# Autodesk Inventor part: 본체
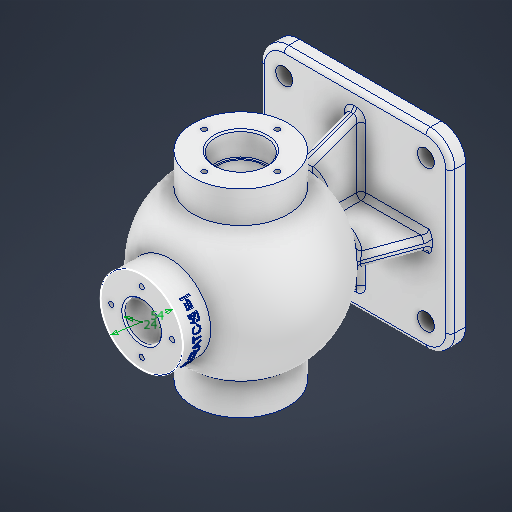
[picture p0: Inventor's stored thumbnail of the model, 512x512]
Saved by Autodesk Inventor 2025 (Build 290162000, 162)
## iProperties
Created: 2025-08
Part Number: 본체
Material: 알루미늄 6061
Document SubType Name: Modeling
Designer: infra012
Density: 2.7 g/cm^3
Appearance: 알루미늄 - 평지
Mass: 1540.2 g
Surface Area: 1173.87 cm^2
Volume: 570.444 cm^3
Author: infra012
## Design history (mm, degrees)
sketch "스케치2"
  geometry: L1 (-62.5, -62.5)-(62.5, -62.5); L2 (62.5, -62.5)-(62.5, 62.5); L3 (62.5, 62.5)-(-62.5, 62.5); L4 (-62.5, 62.5)-(-62.5, -62.5); L5 (-62.5, -62.5)-(62.5, 62.5); L6 (62.5, -62.5)-(-62.5, 62.5); 1 further point
  constraints: 12 end point, 2 midpoint, 2 parallel, 1 horizontal, 1 perpendicular
  dimensions: "d0" = 125 distance of L3.end L2.end; "d1" = 125 distance of L2.end L1.end
extrude "돌출1" new body sketch "스케치2" distance "d2" = 10; taper "d3" = 0 deg
sketch "스케치3"
  geometry: L1 (8.5, 85)-(116.5, 85); L2 (0, 0)-(125, 0) reference; A1 r 44 centre (62.5, 85) between (106.5, 85) and (18.5, 85); A2 r 54 centre (62.5, 85) between (116.5, 85) and (8.5, 85); 3 further points
  constraints: 4 point on circle, 2 centre point, 2 end point, 2 point on line, 1 coincident, 1 horizontal alignment, 1 midpoint
  dimensions: "d4" = 88 diameter of A1; "d5" = 108 diameter of A2; "d7" = 85 distance from line of L2 A1.centre
revolve "회전1" sketch "스케치3" stored, may be unused: angle "d8" = 90 deg
node "작업 평면1"
sketch "스케치4"
  geometry: C1 r 27 at (0, 0); C2 r 12 at (0, 0); 1 further point
  constraints: 2 centre point, 2 coincident
  dimensions: "d10" = 54 diameter of C1; "d11" = 24 diameter of C2
extrude "돌출2" join sketch "스케치4" stored distance "d12" = 10; taper "d13" = 0 deg
node "작업 평면3"
sketch "스케치5"
  geometry: L1 (-27, 131.765)-(27, 131.765) reference; C1 r 31 at (0, 85); A1 r 54 centre (0, 85) between (-27, 131.765) and (27, 131.765) reference; 1 further point
  constraints: 1 centre point, 1 coincident
  dimensions: "d16" = 62 diameter of C1
extrude "돌출3" join sketch "스케치5" stored distance "d18" = 10; taper "d19" = 0 deg
node "작업 평면4"
sketch "스케치6"
  geometry: C1 r 31 at (0, 85) reference; 1 further point
extrude "돌출4" join sketch "스케치6" stored distance "d21" = 10; taper "d22" = 0 deg
sketch "스케치7"
  geometry: C1 r 31 at (0, 0) reference; C2 r 15 at (0, 0); 1 further point
  constraints: 1 centre point, 1 coincident
  dimensions: "d23" = 30 diameter of C2
extrude "돌출5" cut sketch "스케치7" extent not by distance; stored distance "d24" = 0; taper "d25" = 0 deg
sketch "스케치8"
  geometry: C1 r 31 at (0, 0) reference; C2 r 16.5 at (0, 0); 1 further point
  constraints: 1 centre point, 1 coincident
  dimensions: "d26" = 33 diameter of C2
hole "구멍1" sketch "스케치8" at (0, 0) diameter "d27" = 33; stored, may be unused: countersink angle "d31" = 90 deg, drill point angle "d33" = 0 deg; dims "d28" = 12, "d29" = 33, "d30" = 1, "d32" = 16
sketch "스케치9"
  geometry: C1 r 16.5 at (0, 0) reference; 1 further point
hole "구멍2" sketch "스케치9" at (0, 0) diameter "d34" = 33; stored, may be unused: countersink angle "d38" = 90 deg, drill point angle "d40" = 0 deg; dims "d35" = 6, "d36" = 4, "d37" = 2, "d39" = 16
hole "구멍3" sketch "스케치4" diameter "d41" = 24; stored, may be unused: countersink angle "d45" = 90 deg, drill point angle "d47" = 0 deg; dims "d42" = 6, "d43" = 4, "d44" = 2, "d46" = 84.075
sketch "스케치11"
  geometry: L1 (-33.559, 56.544)-(-50.5, 10); L2 (33.559, 56.544)-(50.5, 10); L3 (-62.5, 0)-(-62.5, 10) reference; L4 (62.5, 0)-(62.5, 10) reference; L5 (62.5, 10)-(-62.5, 10) reference; A1 r 44 centre (0, 85) between (-41.364, 70) and (-41.364, 100) reference; 1 further point
  constraints: 4 end point, 2 point on circle, 2 point on line
  dimensions: "d48" = 20 deg angle of L3 L1; "d49" = 20 deg angle of L4 L2; "d50" = 12 distance from line of L1.end L3; "d51" = 12 distance from line of L4 L2.end
sketch "스케치12"
  geometry: L1 (-33.559, 56.544)-(-50.5, 10); L2 (33.559, 56.544)-(50.5, 10); L3 (-62.5, 0)-(-62.5, 10) reference; L4 (62.5, 0)-(62.5, 10) reference; L5 (62.5, 10)-(-62.5, 10) reference; A1 r 44 centre (0, 85) between (-12, 127.332) and (12, 127.332) reference; 1 further point
  constraints: 4 end point, 2 point on circle, 2 point on line
  dimensions: "d54" = 20 deg angle of L3 L1; "d55" = 20 deg angle of L4 L2; "d56" = 12 distance from line of L1.end L3; "d57" = 12 distance from line of L4 L2.end
sketch "스케치13" dims "d60" = 40
  geometry: L1 (0, 0)-(4, 4) reference; 5 further points
  constraints: 1 coincident, 1 horizontal alignment, 7 other
  dimensions: "d63" = 360 deg dimension on L1.start point (20, 0) (derived)
hole "구멍4" sketch "스케치13" at (20, 0), (0, -20), (-20, 0), (0, 20) diameter "d65" = 3.242; stored, may be unused: countersink angle "d69" = 90 deg, drill point angle "d71" = 118 deg; dims "d66" = 9, "d67" = 4, "d68" = 2, "d70" = 11
sketch "스케치14" dims "d72" = 48
  geometry: C1 r 15 at (0, 0) reference; 6 further points
  constraints: 1 coincident, 1 vertical alignment, 7 other
  dimensions: "d75" = 360 deg dimension on point (0, 0) point (0, -24) (derived)
hole "구멍5" sketch "스케치14" at (0, -24), (-24, 0), (0, 24), (24, 0) diameter "d77" = 3.242; stored, may be unused: countersink angle "d81" = 90 deg, drill point angle "d83" = 118 deg; dims "d78" = 12, "d79" = 4, "d80" = 2, "d82" = 15
sketch "스케치15"
  geometry: C1 r 1.621 at (0, 24) reference; C2 r 1.621 at (24, 0) reference; C3 r 1.621 at (-24, 0) reference; C4 r 1.621 at (0, -24) reference; 1 further point
hole "구멍6" sketch "스케치15" at (0, 24), (24, 0), (0, -24), (-24, 0) diameter "d84" = 3.242; stored, may be unused: countersink angle "d88" = 90 deg, drill point angle "d90" = 118 deg; dims "d85" = 12, "d86" = 4, "d87" = 2, "d89" = 15
fillet "모깎기1" dims "d91" = 16
fillet "모깎기4" dims "d94" = 3
sketch "스케치16"
  geometry: 1 further point
node "작업 평면5"
sketch "스케치17"
  geometry: L1 (-12.205, 145.584)-(12.205, 145.584); L2 (12.205, 145.584)-(12.205, 136.416); L3 (12.205, 136.416)-(-12.205, 136.416); L4 (-12.205, 136.416)-(-12.205, 145.584); L5 (27, 150)-(-27, 150) reference; 4 further points
  constraints: 3 midpoint, 1 vertical alignment, 2 other
  dimensions: "d96" = 9 distance from line of L5 point (-12.205, 141)
sketch "스케치18"
  geometry: L1 (46.5, 46.5)-(-46.5, 46.5); L2 (-46.5, 46.5)-(-46.5, -46.5); L3 (-46.5, -46.5)-(46.5, -46.5); L4 (46.5, -46.5)-(46.5, 46.5); L5 (46.5, 46.5)-(-46.5, -46.5); L6 (-46.5, 46.5)-(46.5, -46.5); 5 further points
  constraints: 12 end point, 4 coincident, 2 midpoint, 2 parallel, 1 horizontal, 1 perpendicular
  dimensions: "d102" = 93 distance of L3.end L2.end; "d103" = 93 distance of L2.end L1.end
hole "구멍7" sketch "스케치18" at (46.5, -46.5), (46.5, 46.5), (-46.5, 46.5), (-46.5, -46.5) diameter "d104" = 11; stored, may be unused: countersink angle "d108" = 90 deg, drill point angle "d110" = 118 deg; dims "d105" = 12, "d106" = 4, "d107" = 2, "d109" = 15
chamfer "모따기1" distance "d111" = 1; stored, may be unused: second distance "d112" = 2, angle "d113" = 45 deg
chamfer "모따기2" distance "d114" = 1; stored, may be unused: second distance "d115" = 2, angle "d116" = 45 deg
chamfer "모따기3" distance "d117" = 1; stored, may be unused: second distance "d118" = 2, angle "d119" = 45 deg
extrude "돌출8" join sketch "스케치11" stored distance "d120" = 8; taper "d121" = 0 deg
fillet "모깎기5" dims "d122" = 3
fillet "모깎기6" dims "d123" = 3
extrude "돌출9" join sketch "스케치12" stored distance "d125" = 8; taper "d126" = 0 deg
fillet "모깎기8" dims "d127" = 3
fillet "모깎기9" dims "d128" = 3
fillet "모깎기10" dims "d129" = 0.6
fillet "모깎기11" dims "d130" = 0.6
feature "엠보싱3" dims "d10" = 54, "d11" = 24, "d131" = 0.5, "d132" = 0
node "솔리드1"
node "투영된 루프1"
node "스케치 - 원형 패턴1" dims "d63" = 360 deg (derived)
node "스케치 - 원형 패턴2" dims "d75" = 360 deg (derived)
feature "A9D066F2-1C7D-4E18-AEED-F7BC21143FA4" dims "d27" = 33, "d28" = 12, "d29" = 33, "d30" = 1, "d31" = 90 deg, "d32" = 16, "d33" = 0
other parameters: "d15" = 65, "d20" = -65, "d95" = 62.5
